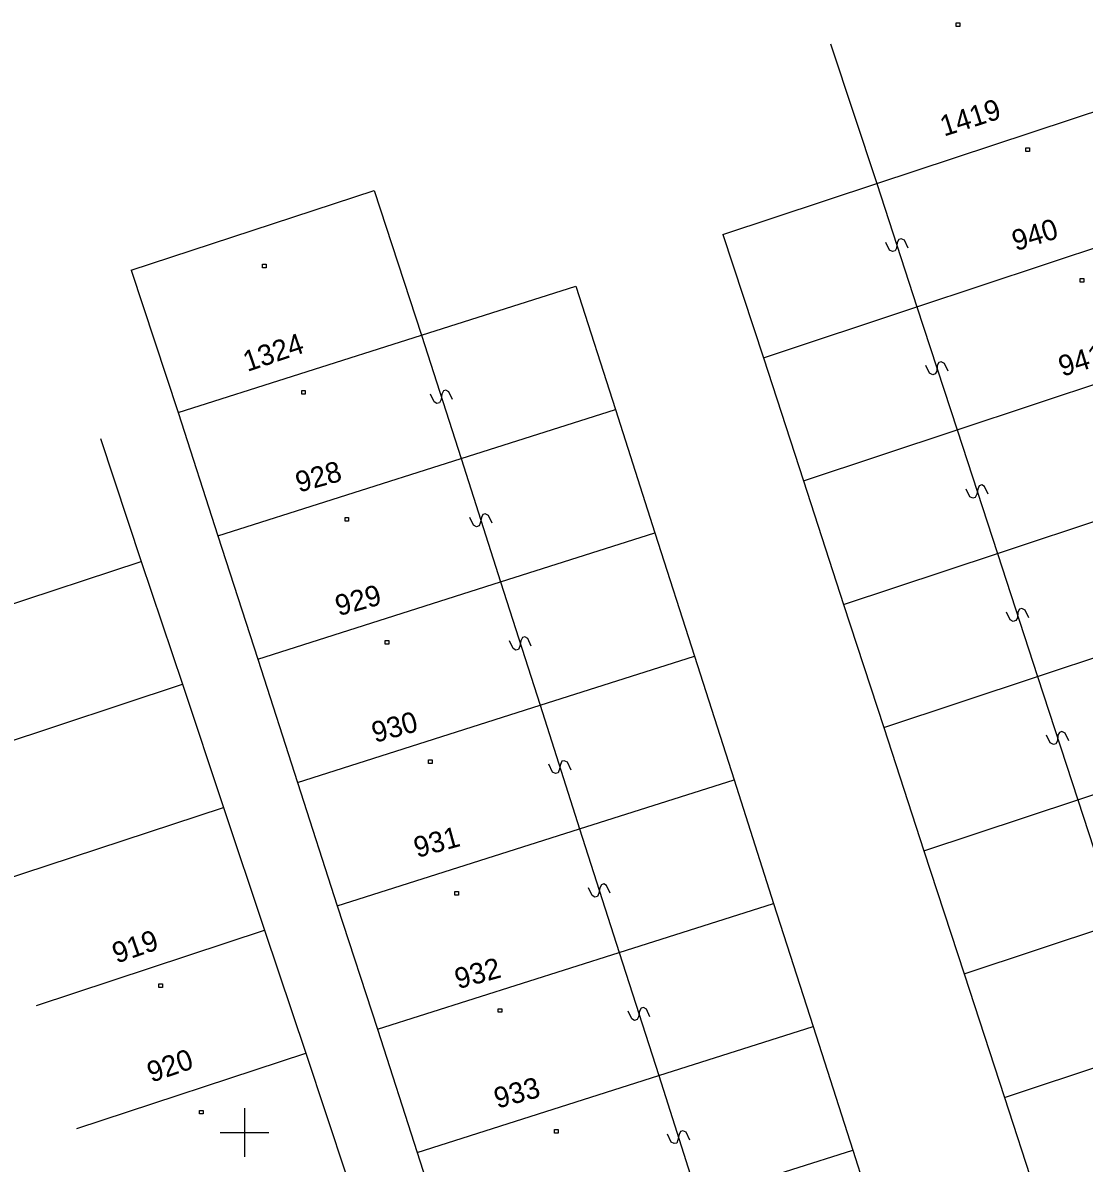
# Model space of a CAD drawing. Extents: x -493352 to -492964, y -1127001 to -1126712.
# Drawn here: x -493295.47 to -493269.27, y -1126740.75 to -1126712.6 of the extents above; entities that cross this region are included whole.
import ezdxf

# ---------------------------------------------------------------- set-up
doc = ezdxf.new("R2010")
doc.units = 0
doc.layers.add('katastrální mapa', color=7, linetype='Continuous')
doc.layers.add('síť', color=7, linetype='Continuous')

msp = doc.modelspace()

# ---------------------------------------------------------------- linework, layer by layer
at = {"layer": 'katastrální mapa'}
for p, q in [((-493272.43, -1126712.6), (-493272.34, -1126712.6)), ((-493272.43, -1126712.69), (-493272.43, -1126712.6)), ((-493272.34, -1126712.69), (-493272.43, -1126712.69)), ((-493272.34, -1126712.6), (-493272.34, -1126712.69)), ((-493275.53, -1126713.12), (-493274.39, -1126716.57)), ((-493274.39, -1126716.57), (-493268.45, -1126714.6)), ((-493270.71, -1126715.69), (-493270.62, -1126715.69)), ((-493270.71, -1126715.78), (-493270.71, -1126715.69)), ((-493270.62, -1126715.78), (-493270.71, -1126715.78)), ((-493270.62, -1126715.69), (-493270.62, -1126715.78)), ((-493278.19, -1126717.83), (-493274.39, -1126716.57)), ((-493274.39, -1126716.57), (-493273.4, -1126719.61)), ((-493292.8, -1126718.71), (-493286.8, -1126716.74)), ((-493286.8, -1126716.74), (-493285.63, -1126720.31)), ((-493273.4, -1126719.61), (-493267.46, -1126717.64)), ((-493278.19, -1126717.83), (-493277.19, -1126720.87)), ((-493274.08, -1126718.21), (-493274.17, -1126718.02)), ((-493273.89, -1126718.02), (-493273.9, -1126718.16)), ((-493273.85, -1126717.95), (-493273.89, -1126718.02)), ((-493273.79, -1126717.93), (-493273.85, -1126717.95)), ((-493273.71, -1126717.97), (-493273.79, -1126717.93)), ((-493273.62, -1126718.16), (-493273.71, -1126717.97)), ((-493274, -1126718.25), (-493274.08, -1126718.21)), ((-493273.94, -1126718.23), (-493274, -1126718.25)), ((-493273.9, -1126718.16), (-493273.94, -1126718.23)), ((-493289.56, -1126718.56), (-493289.47, -1126718.56)), ((-493289.56, -1126718.65), (-493289.56, -1126718.56)), ((-493289.47, -1126718.56), (-493289.47, -1126718.65)), ((-493292.8, -1126718.71), (-493291.64, -1126722.22)), ((-493289.47, -1126718.65), (-493289.56, -1126718.65)), ((-493285.63, -1126720.31), (-493281.82, -1126719.1)), ((-493281.82, -1126719.1), (-493280.84, -1126722.15)), ((-493269.37, -1126718.91), (-493269.28, -1126718.91)), ((-493269.37, -1126719), (-493269.37, -1126718.91)), ((-493269.28, -1126719), (-493269.37, -1126719)), ((-493269.28, -1126718.91), (-493269.28, -1126719)), ((-493277.19, -1126720.87), (-493273.4, -1126719.61)), ((-493273.4, -1126719.61), (-493272.41, -1126722.65)), ((-493291.64, -1126722.22), (-493285.63, -1126720.31)), ((-493285.63, -1126720.31), (-493284.65, -1126723.36)), ((-493272.41, -1126722.65), (-493266.47, -1126720.68)), ((-493277.19, -1126720.87), (-493276.2, -1126723.91)), ((-493273.09, -1126721.25), (-493273.18, -1126721.06)), ((-493272.9, -1126721.06), (-493272.91, -1126721.2)), ((-493272.86, -1126720.99), (-493272.9, -1126721.06)), ((-493272.8, -1126720.97), (-493272.86, -1126720.99)), ((-493272.72, -1126721.01), (-493272.8, -1126720.97)), ((-493272.63, -1126721.2), (-493272.72, -1126721.01)), ((-493273.01, -1126721.29), (-493273.09, -1126721.25)), ((-493272.95, -1126721.27), (-493273.01, -1126721.29)), ((-493272.91, -1126721.2), (-493272.95, -1126721.27)), ((-493288.59, -1126721.68), (-493288.5, -1126721.68)), ((-493288.59, -1126721.77), (-493288.59, -1126721.68)), ((-493288.5, -1126721.68), (-493288.5, -1126721.77)), ((-493285.09, -1126721.69), (-493285.13, -1126721.77)), ((-493285.03, -1126721.67), (-493285.09, -1126721.69)), ((-493284.96, -1126721.71), (-493285.03, -1126721.67)), ((-493284.87, -1126721.9), (-493284.96, -1126721.71)), ((-493288.5, -1126721.77), (-493288.59, -1126721.77)), ((-493285.32, -1126721.96), (-493285.41, -1126721.77)), ((-493285.25, -1126722), (-493285.32, -1126721.96)), ((-493285.19, -1126721.98), (-493285.25, -1126722)), ((-493285.15, -1126721.9), (-493285.19, -1126721.98)), ((-493285.13, -1126721.77), (-493285.15, -1126721.9)), ((-493291.64, -1126722.22), (-493290.66, -1126725.27)), ((-493284.65, -1126723.36), (-493280.84, -1126722.15)), ((-493280.84, -1126722.15), (-493279.87, -1126725.19)), ((-493276.2, -1126723.91), (-493272.41, -1126722.65)), ((-493272.41, -1126722.65), (-493271.41, -1126725.7)), ((-493293.56, -1126722.86), (-493292.55, -1126725.9)), ((-493290.66, -1126725.27), (-493284.65, -1126723.36)), ((-493284.65, -1126723.36), (-493283.68, -1126726.4)), ((-493276.2, -1126723.91), (-493275.21, -1126726.96)), ((-493271.41, -1126725.7), (-493265.47, -1126723.73)), ((-493272.09, -1126724.3), (-493272.18, -1126724.11)), ((-493271.92, -1126724.24), (-493271.96, -1126724.32)), ((-493271.9, -1126724.11), (-493271.92, -1126724.24)), ((-493271.86, -1126724.03), (-493271.9, -1126724.11)), ((-493271.8, -1126724.01), (-493271.86, -1126724.03)), ((-493271.73, -1126724.05), (-493271.8, -1126724.01)), ((-493271.64, -1126724.24), (-493271.73, -1126724.05)), ((-493272.02, -1126724.34), (-493272.09, -1126724.3)), ((-493271.96, -1126724.32), (-493272.02, -1126724.34)), ((-493284.12, -1126724.74), (-493284.15, -1126724.81)), ((-493284.06, -1126724.72), (-493284.12, -1126724.74)), ((-493283.98, -1126724.76), (-493284.06, -1126724.72)), ((-493283.89, -1126724.95), (-493283.98, -1126724.76)), ((-493287.52, -1126724.81), (-493287.43, -1126724.81)), ((-493287.52, -1126724.9), (-493287.52, -1126724.81)), ((-493287.43, -1126724.9), (-493287.52, -1126724.9)), ((-493287.43, -1126724.81), (-493287.43, -1126724.9)), ((-493284.35, -1126725), (-493284.44, -1126724.81)), ((-493284.27, -1126725.04), (-493284.35, -1126725)), ((-493284.21, -1126725.02), (-493284.27, -1126725.04)), ((-493284.18, -1126724.95), (-493284.21, -1126725.02)), ((-493284.15, -1126724.81), (-493284.18, -1126724.95)), ((-493290.66, -1126725.27), (-493289.67, -1126728.31)), ((-493283.68, -1126726.4), (-493279.87, -1126725.19)), ((-493279.87, -1126725.19), (-493278.89, -1126728.24)), ((-493298.16, -1126727.75), (-493292.55, -1126725.9)), ((-493292.55, -1126725.9), (-493291.53, -1126728.93)), ((-493275.21, -1126726.96), (-493271.41, -1126725.7)), ((-493271.41, -1126725.7), (-493270.42, -1126728.74)), ((-493289.67, -1126728.31), (-493283.68, -1126726.4)), ((-493283.68, -1126726.4), (-493282.7, -1126729.45)), ((-493270.42, -1126728.74), (-493264.48, -1126726.77)), ((-493275.21, -1126726.96), (-493274.22, -1126730)), ((-493270.81, -1126727.06), (-493270.87, -1126727.08)), ((-493270.73, -1126727.1), (-493270.81, -1126727.06)), ((-493271.1, -1126727.34), (-493271.19, -1126727.15)), ((-493271.02, -1126727.38), (-493271.1, -1126727.34)), ((-493270.92, -1126727.29), (-493270.96, -1126727.36)), ((-493270.91, -1126727.15), (-493270.92, -1126727.29)), ((-493270.87, -1126727.08), (-493270.91, -1126727.15)), ((-493270.64, -1126727.29), (-493270.73, -1126727.1)), ((-493270.96, -1126727.36), (-493271.02, -1126727.38)), ((-493286.53, -1126727.85), (-493286.44, -1126727.85)), ((-493286.53, -1126727.94), (-493286.53, -1126727.85)), ((-493286.44, -1126727.85), (-493286.44, -1126727.94)), ((-493283.37, -1126728.05), (-493283.46, -1126727.86)), ((-493283.18, -1126727.86), (-493283.2, -1126727.99)), ((-493283.14, -1126727.78), (-493283.18, -1126727.86)), ((-493283.08, -1126727.76), (-493283.14, -1126727.78)), ((-493283.01, -1126727.8), (-493283.08, -1126727.76)), ((-493282.92, -1126727.99), (-493283.01, -1126727.8)), ((-493286.44, -1126727.94), (-493286.53, -1126727.94)), ((-493283.3, -1126728.09), (-493283.37, -1126728.05)), ((-493283.24, -1126728.07), (-493283.3, -1126728.09)), ((-493283.2, -1126727.99), (-493283.24, -1126728.07)), ((-493289.67, -1126728.31), (-493288.69, -1126731.36)), ((-493282.7, -1126729.45), (-493278.89, -1126728.24)), ((-493278.89, -1126728.24), (-493277.91, -1126731.29)), ((-493274.22, -1126730), (-493270.42, -1126728.74)), ((-493270.42, -1126728.74), (-493269.43, -1126731.78)), ((-493297.16, -1126730.79), (-493291.53, -1126728.93)), ((-493291.53, -1126728.93), (-493290.52, -1126731.97)), ((-493288.69, -1126731.36), (-493282.7, -1126729.45)), ((-493282.7, -1126729.45), (-493281.73, -1126732.5)), ((-493269.43, -1126731.78), (-493263.49, -1126729.81)), ((-493274.22, -1126730), (-493273.23, -1126733.04)), ((-493269.88, -1126730.12), (-493269.92, -1126730.19)), ((-493269.82, -1126730.1), (-493269.88, -1126730.12)), ((-493269.74, -1126730.14), (-493269.82, -1126730.1)), ((-493269.65, -1126730.33), (-493269.74, -1126730.14)), ((-493270.11, -1126730.38), (-493270.2, -1126730.19)), ((-493270.03, -1126730.42), (-493270.11, -1126730.38)), ((-493269.97, -1126730.4), (-493270.03, -1126730.42)), ((-493269.93, -1126730.33), (-493269.97, -1126730.4)), ((-493269.92, -1126730.19), (-493269.93, -1126730.33)), ((-493285.46, -1126730.8), (-493285.37, -1126730.8)), ((-493285.46, -1126730.89), (-493285.46, -1126730.8)), ((-493285.37, -1126730.89), (-493285.46, -1126730.89)), ((-493285.37, -1126730.8), (-493285.37, -1126730.89)), ((-493282.4, -1126731.1), (-493282.49, -1126730.9)), ((-493282.2, -1126730.91), (-493282.23, -1126731.04)), ((-493282.17, -1126730.83), (-493282.2, -1126730.91)), ((-493282.11, -1126730.82), (-493282.17, -1126730.83)), ((-493282.03, -1126730.85), (-493282.11, -1126730.82)), ((-493281.94, -1126731.05), (-493282.03, -1126730.85)), ((-493282.32, -1126731.13), (-493282.4, -1126731.1)), ((-493282.26, -1126731.12), (-493282.32, -1126731.13)), ((-493282.23, -1126731.04), (-493282.26, -1126731.12)), ((-493288.69, -1126731.36), (-493287.71, -1126734.4)), ((-493281.73, -1126732.5), (-493277.91, -1126731.29)), ((-493277.91, -1126731.29), (-493276.94, -1126734.34)), ((-493273.23, -1126733.04), (-493269.43, -1126731.78)), ((-493269.43, -1126731.78), (-493268.44, -1126734.82)), ((-493296.15, -1126733.82), (-493290.52, -1126731.97)), ((-493290.52, -1126731.97), (-493289.51, -1126735)), ((-493287.71, -1126734.4), (-493281.73, -1126732.5)), ((-493281.73, -1126732.5), (-493280.75, -1126735.55)), ((-493273.23, -1126733.04), (-493272.23, -1126736.08)), ((-493284.81, -1126734.05), (-493284.72, -1126734.05)), ((-493284.81, -1126734.14), (-493284.81, -1126734.05)), ((-493284.72, -1126734.05), (-493284.72, -1126734.14)), ((-493281.42, -1126734.15), (-493281.51, -1126733.96)), ((-493281.25, -1126734.09), (-493281.29, -1126734.17)), ((-493281.23, -1126733.96), (-493281.25, -1126734.09)), ((-493281.19, -1126733.88), (-493281.23, -1126733.96)), ((-493281.13, -1126733.86), (-493281.19, -1126733.88)), ((-493281.06, -1126733.9), (-493281.13, -1126733.86)), ((-493280.97, -1126734.09), (-493281.06, -1126733.9)), ((-493284.72, -1126734.14), (-493284.81, -1126734.14)), ((-493281.35, -1126734.19), (-493281.42, -1126734.15)), ((-493281.29, -1126734.17), (-493281.35, -1126734.19)), ((-493280.75, -1126735.55), (-493276.94, -1126734.34)), ((-493276.94, -1126734.34), (-493275.96, -1126737.38)), ((-493287.71, -1126734.4), (-493286.72, -1126737.45)), ((-493272.23, -1126736.08), (-493268.44, -1126734.82)), ((-493295.14, -1126736.86), (-493289.51, -1126735)), ((-493289.51, -1126735), (-493288.49, -1126738.04)), ((-493286.72, -1126737.45), (-493280.75, -1126735.55)), ((-493280.75, -1126735.55), (-493279.77, -1126738.59)), ((-493292.12, -1126736.33), (-493292.03, -1126736.33)), ((-493292.12, -1126736.42), (-493292.12, -1126736.33)), ((-493292.03, -1126736.33), (-493292.03, -1126736.42)), ((-493272.23, -1126736.08), (-493271.24, -1126739.13)), ((-493292.03, -1126736.42), (-493292.12, -1126736.42)), ((-493280.15, -1126736.91), (-493280.21, -1126736.93)), ((-493280.08, -1126736.95), (-493280.15, -1126736.91)), ((-493283.74, -1126736.94), (-493283.65, -1126736.94)), ((-493283.74, -1126737.03), (-493283.74, -1126736.94)), ((-493283.65, -1126737.03), (-493283.74, -1126737.03)), ((-493283.65, -1126736.94), (-493283.65, -1126737.03)), ((-493280.44, -1126737.19), (-493280.53, -1126737)), ((-493280.37, -1126737.23), (-493280.44, -1126737.19)), ((-493280.27, -1126737.14), (-493280.31, -1126737.21)), ((-493280.25, -1126737), (-493280.27, -1126737.14)), ((-493280.21, -1126736.93), (-493280.25, -1126737)), ((-493279.99, -1126737.14), (-493280.08, -1126736.95)), ((-493286.72, -1126737.45), (-493285.74, -1126740.49)), ((-493280.31, -1126737.21), (-493280.37, -1126737.23)), ((-493279.77, -1126738.59), (-493275.96, -1126737.38)), ((-493275.96, -1126737.38), (-493274.98, -1126740.43)), ((-493294.14, -1126739.9), (-493288.49, -1126738.04)), ((-493288.49, -1126738.04), (-493287.48, -1126741.07)), ((-493271.24, -1126739.13), (-493267.45, -1126737.87)), ((-493285.74, -1126740.49), (-493279.77, -1126738.59)), ((-493279.77, -1126738.59), (-493278.8, -1126741.64)), ((-493271.24, -1126739.13), (-493270.25, -1126742.17)), ((-493291.11, -1126739.45), (-493291.02, -1126739.45)), ((-493291.11, -1126739.54), (-493291.11, -1126739.45)), ((-493291.02, -1126739.54), (-493291.11, -1126739.54)), ((-493291.02, -1126739.45), (-493291.02, -1126739.54)), ((-493282.35, -1126739.92), (-493282.26, -1126739.92)), ((-493282.35, -1126740.01), (-493282.35, -1126739.92)), ((-493282.26, -1126740.01), (-493282.35, -1126740.01)), ((-493282.26, -1126739.92), (-493282.26, -1126740.01)), ((-493279.24, -1126739.97), (-493279.27, -1126740.05)), ((-493279.18, -1126739.96), (-493279.24, -1126739.97)), ((-493279.1, -1126739.99), (-493279.18, -1126739.96)), ((-493279.01, -1126740.19), (-493279.1, -1126739.99)), ((-493279.47, -1126740.24), (-493279.56, -1126740.04)), ((-493279.39, -1126740.27), (-493279.47, -1126740.24)), ((-493279.33, -1126740.26), (-493279.39, -1126740.27)), ((-493279.3, -1126740.18), (-493279.33, -1126740.26)), ((-493279.27, -1126740.05), (-493279.3, -1126740.18)), ((-493285.74, -1126740.49), (-493284.76, -1126743.54)), ((-493278.8, -1126741.64), (-493274.98, -1126740.43)), ((-493274.98, -1126740.43), (-493274.01, -1126743.48))]:
    msp.add_line(p, q, dxfattribs=at)
at = {"layer": 'síť'}
for p, q in [((-493290, -1126739.4), (-493290, -1126740.6)), ((-493290.6, -1126740), (-493289.4, -1126740))]:
    msp.add_line(p, q, dxfattribs=at)

# ---------------------------------------------------------------- texts
at = {"layer": 'katastrální mapa'}
for s, rotation, p in [('1419', 17.703, (-493272.73, -1126715.41)), ('940', 17.073, (-493270.96, -1126718.24)), ('1324', 18.792, (-493289.93, -1126721.22)), ('941', 17.073, (-493269.81, -1126721.34)), ('928', 15.354, (-493288.66, -1126724.2)), ('929', 15.354, (-493287.68, -1126727.25)), ('930', 15.354, (-493286.78, -1126730.38)), ('931', 15.354, (-493285.74, -1126733.22)), ('919', 18.963, (-493293.16, -1126735.83)), ('932', 15.354, (-493284.73, -1126736.46)), ('920', 18.963, (-493292.3, -1126738.77)), ('933', 15.354, (-493283.76, -1126739.41))]:
    msp.add_text(s, height=0.51, rotation=rotation, dxfattribs=at).set_placement(p)

doc.saveas('drawing.dxf')
